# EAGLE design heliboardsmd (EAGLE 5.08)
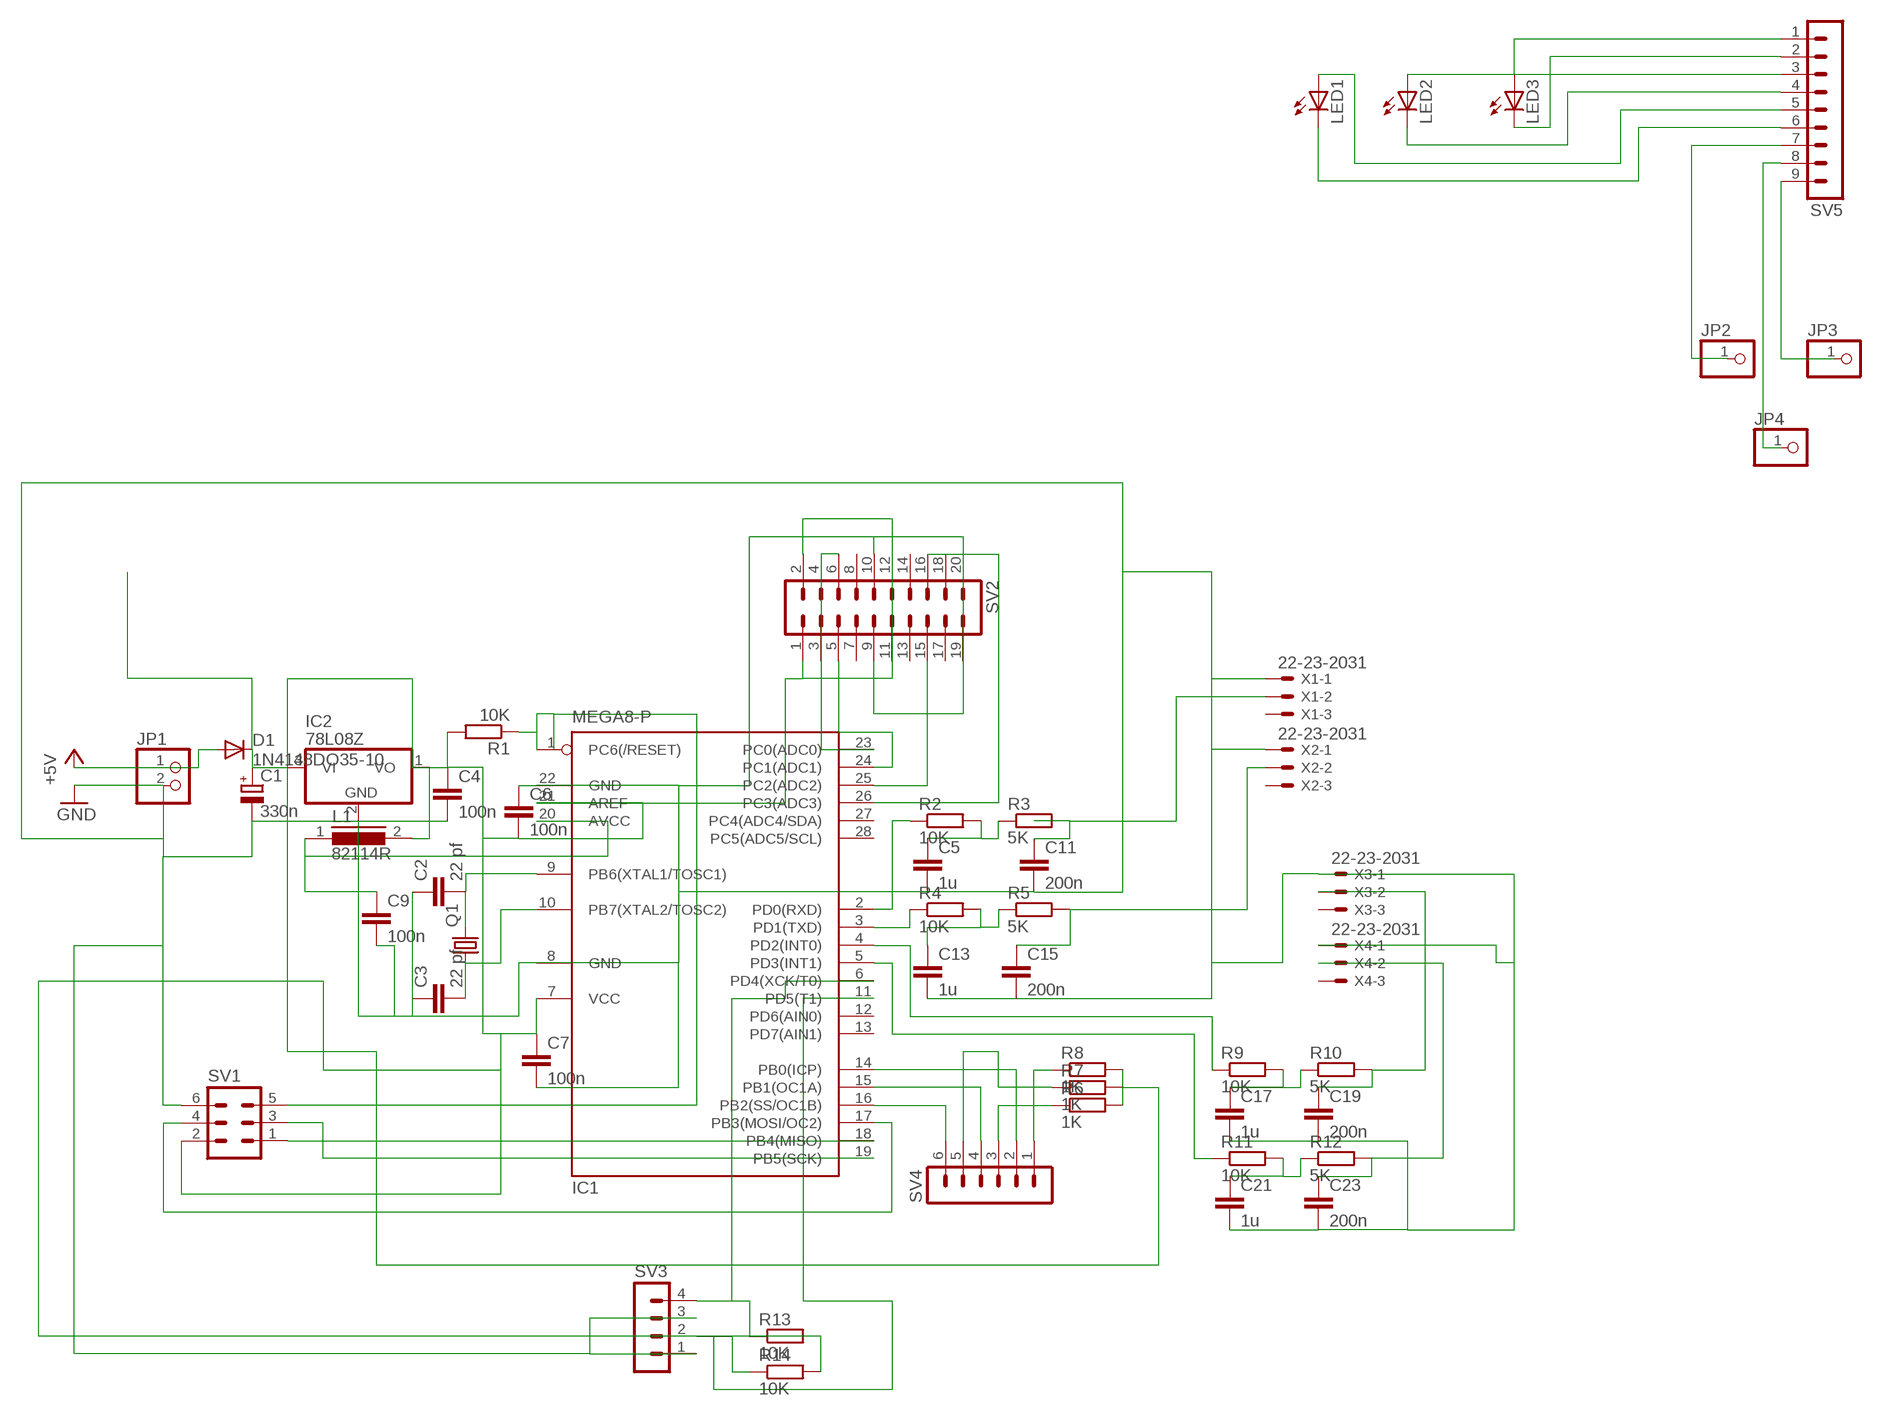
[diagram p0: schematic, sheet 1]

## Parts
C1  330n  CPOL-EUE1.8-4  [E1,8-4]
C2  22 pf  C-EUC0805K  [C0805K]
C3  22 pf  C-EUC0805K  [C0805K]
C4  100n  C-EUC0805K  [C0805K]
C5  1u  C-EUC1206K  [C1206K]
C6  100n  C-EUC0805K  [C0805K]
C7  100n  C-EUC0805K  [C0805K]
C9  100n  C-EUC0805K  [C0805K]
C11  200n  C-EUC1206K  [C1206K]
C13  1u  C-EUC1206K  [C1206K]
C15  200n  C-EUC1206K  [C1206K]
C17  1u  C-EUC1206K  [C1206K]
C19  200n  C-EUC1206K  [C1206K]
C21  1u  C-EUC1206K  [C1206K]
C23  200n  C-EUC1206K  [C1206K]
D1  1N4148DO35-10  [DO35-10]
IC1  MEGA8-P  [DIL28-3]
IC2  78L08Z  [TO92]
JP1  PINHD-1X2/90  [1X02/90]
JP2  PINHD-1X1  [1X01]
JP3  PINHD-1X1  [1X01]
JP4  PINHD-1X1  [1X01]
L1  82114R  [82114R]
LED1  LED3MM  [LED3MM]
LED2  LED3MM  [LED3MM]
LED3  LED3MM  [LED3MM]
Q1  CRYSTALHC18U-V  [HC18U-V]
R1  10K  R-EU_R1206  [R1206]
R2  10K  R-EU_M0805  [M0805]
R3  5K  R-EU_M0805  [M0805]
R4  10K  R-EU_M0805  [M0805]
R5  5K  R-EU_M0805  [M0805]
R6  1K  R-EU_M1206  [M1206]
R7  1K  R-EU_M1206  [M1206]
R8  1K  R-EU_M1206  [M1206]
R9  10K  R-EU_M0805  [M0805]
R10  5K  R-EU_M0805  [M0805]
R11  10K  R-EU_M0805  [M0805]
R12  5K  R-EU_M0805  [M0805]
R13  10K  R-EU_M0805  [M0805]
R14  10K  R-EU_M0805  [M0805]
SV1  MA03-2  [MA03-2]
SV2  MA10-2  [MA10-2]
SV3  MA04-1  [MA04-1]
SV4  MA06-1  [MA06-1]
SV5  MA09-1  [MA09-1]
X1  22-23-2031  [22-23-2031]
X2  22-23-2031  [22-23-2031]
X3  22-23-2031  [22-23-2031]
X4  22-23-2031  [22-23-2031]

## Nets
+5V: D1.A JP1.1
GND: C1.- C2.1 C3.1 C4.2 C5.2 C6.1 C7.2 C9.2 C11.2 C13.2 C15.2 C17.2 C19.2 C21.2 C23.2 IC1.8(GND) IC1.22(GND) IC2.2(GND) JP1.2 SV1.6 SV2.9 SV2.10 SV2.19 SV2.20 SV3.1 SV3.3 X1.1 X2.1 X3.1 X4.1
N$1: IC1.16(PB2(SS/OC1B)) SV4.6
N$2: C13.1 R4.2 R5.1
N$3: C1.+ D1.C IC2.3(VI)
N$4: C5.1 R2.2 R3.1
N$5: C19.1 R10.2 X3.2
N$7: C23.1 R12.2 X4.2
N$8: R7.1 SV4.5
N$9: C3.2 IC1.10(PB7(XTAL2/TOSC2)) Q1.1
N$10: C2.2 IC1.9(PB6(XTAL1/TOSC1)) Q1.2
N$11: IC1.15(PB1(OC1A)) SV4.4
N$12: R6.1 SV4.3
N$13: IC1.14(PB0(ICP)) SV4.2
N$14: R8.1 SV4.1
N$15: C4.1 C6.2 C7.1 IC1.7(VCC) IC1.21(AREF) IC2.1(VO) L1.2 R1.2 R6.2 R7.2 R8.2 R13.2 R14.2 SV1.2 SV2.1 SV2.2 SV2.11 SV2.12
N$16: IC1.18(PB4(MISO)) SV1.1
N$17: IC1.19(PB5(SCK)) SV1.3
N$18: IC1.17(PB3(MOSI/OC2)) SV1.4
N$19: IC1.2(PD0(RXD)) R2.1
N$20: C9.1 IC1.20(AVCC) L1.1
N$21: C15.1 R5.2 X2.2
N$23: LED3.A SV5.1
N$29: IC1.23(PC0(ADC0)) SV2.6
N$30: IC1.24(PC1(ADC1)) SV2.5
N$31: IC1.26(PC3(ADC3)) SV2.16
N$32: IC1.1(PC6(/RESET)) R1.1 SV1.5
N$33: IC1.25(PC2(ADC2)) SV2.15
N$35: IC1.3(PD1(TXD)) R4.1
N$36: LED3.K(C) SV5.2
N$37: C11.1 R3.2 X1.2
N$39: LED2.A SV5.3
N$41: LED2.K(C) SV5.4
N$42: IC1.4(PD2(INT0)) R9.1
N$43: IC1.5(PD3(INT1)) R11.1
N$44: LED1.A SV5.5
N$46: C17.1 R9.2 R10.1
N$48: C21.1 R11.2 R12.1
N$49: LED1.K(C) SV5.6
N$50: JP2.1 SV5.7
N$51: JP4.1 SV5.8
N$52: JP3.1 SV5.9
N$56: IC1.6(PD4(XCK/T0)) R13.1 SV3.4
N$57: IC1.11(PD5(T1)) R14.1 SV3.2
Unconnected: IC1.12(PD6(AIN0)) IC1.13(PD7(AIN1)) IC1.27(PC4(ADC4/SDA)) IC1.28(PC5(ADC5/SCL)) SV2.3 SV2.4 SV2.7 SV2.8 SV2.13 SV2.14 SV2.17 SV2.18 X1.3 X2.3 X3.3 X4.3

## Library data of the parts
C1 = rcl:CPOL-EU: POLARIZED CAPACITOR, European symbol
C2-C7 C9 C11 C13 C15 C17 C19 C21 C23 = resistor:C-EU: CAPACITOR, European symbol
D1 = diode:1N4148: DIODE
IC1 = atmel:MEGA8-P: MICROCONTROLLER 8 Kbytes FLASH, 1 kbytes SRAM, 512 bytes EEPROM, USART, 4-channel 10 bit ADC, 2-channel 8 bit ADC Pin compatible with Atmega48, ATMega88, ATMega168 Source: avr.lbr
IC2 = linear:78*: Positive VOLTAGE REGULATOR Source: http://cache.national.com/ds/LM/LM78L05.pdf http://www.fairchildsemi.com/ds/LM/LM7805.pdf
JP1 = pinhead:PINHD-1X2: PIN HEADER
JP2-JP4 = pinhead:PINHD-1X1: PIN HEADER
L1 = inductors:82114R: INDUCTOR
LED1-LED3 = led:LED: LED
Q1 = crystal:CRYSTAL: CRYSTAL
R1-R14 = resistor:R-EU_: RESISTOR, European symbol
SV1 = con-lstb:MA03-2: PIN HEADER
SV2 = con-lstb:MA10-2: PIN HEADER
SV3 = con-lstb:MA04-1: PIN HEADER
SV4 = con-lstb:MA06-1: PIN HEADER
SV5 = con-lstb:MA09-1: PIN HEADER
X1-X4 = con-molex:22-23-2031: .100" (2.54mm) Center Header - 3 Pin

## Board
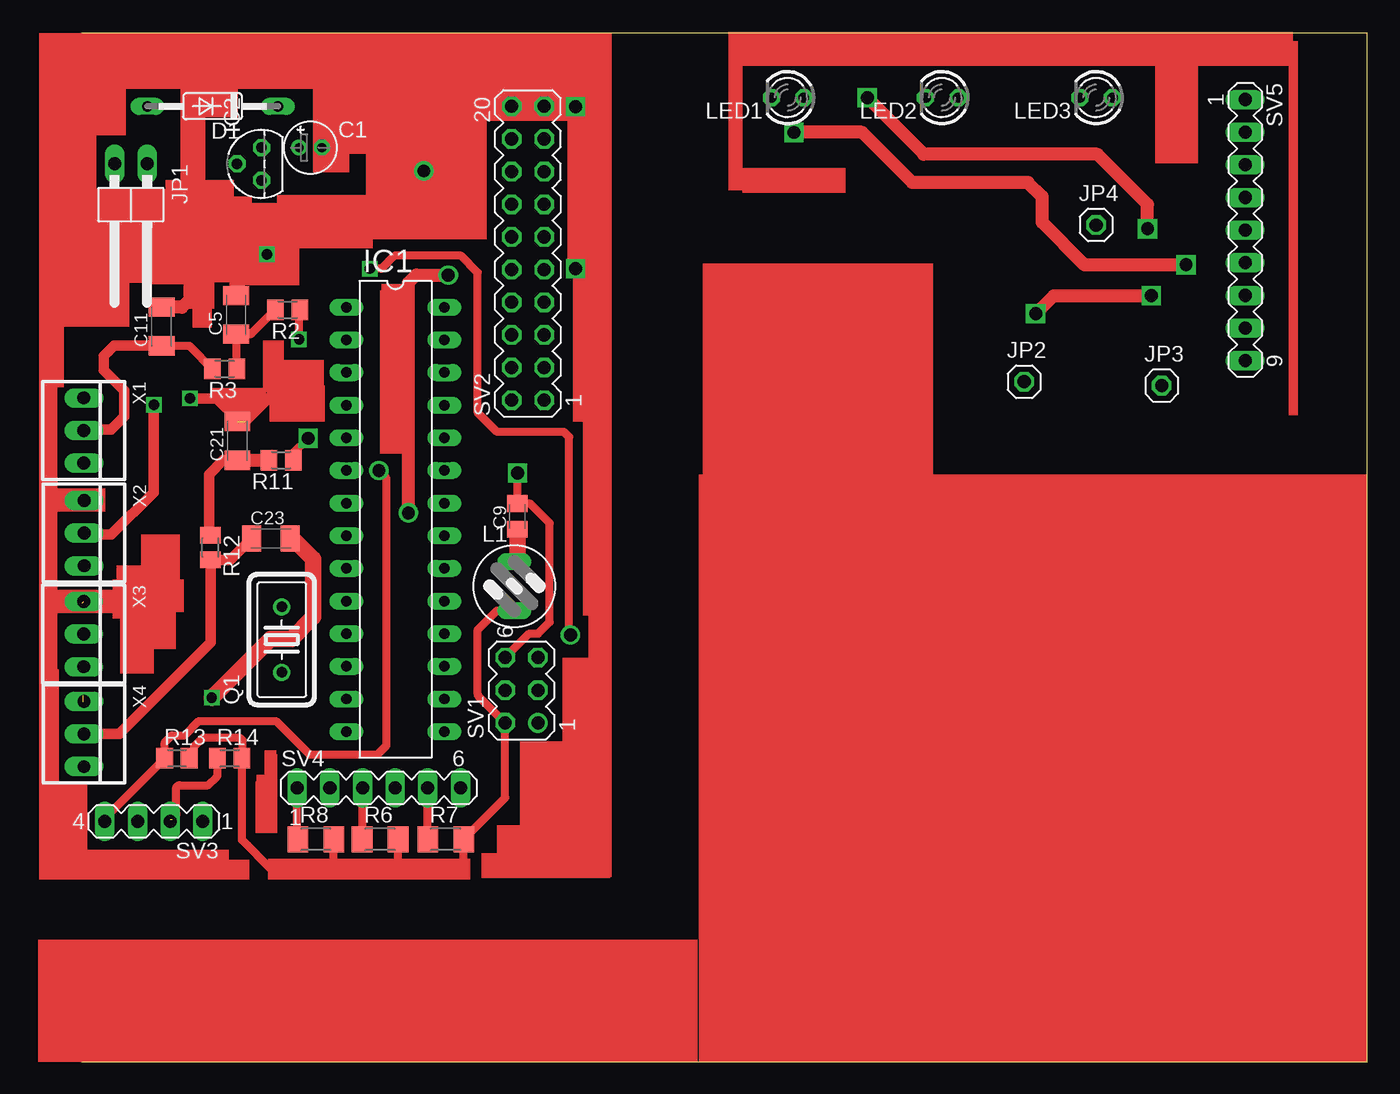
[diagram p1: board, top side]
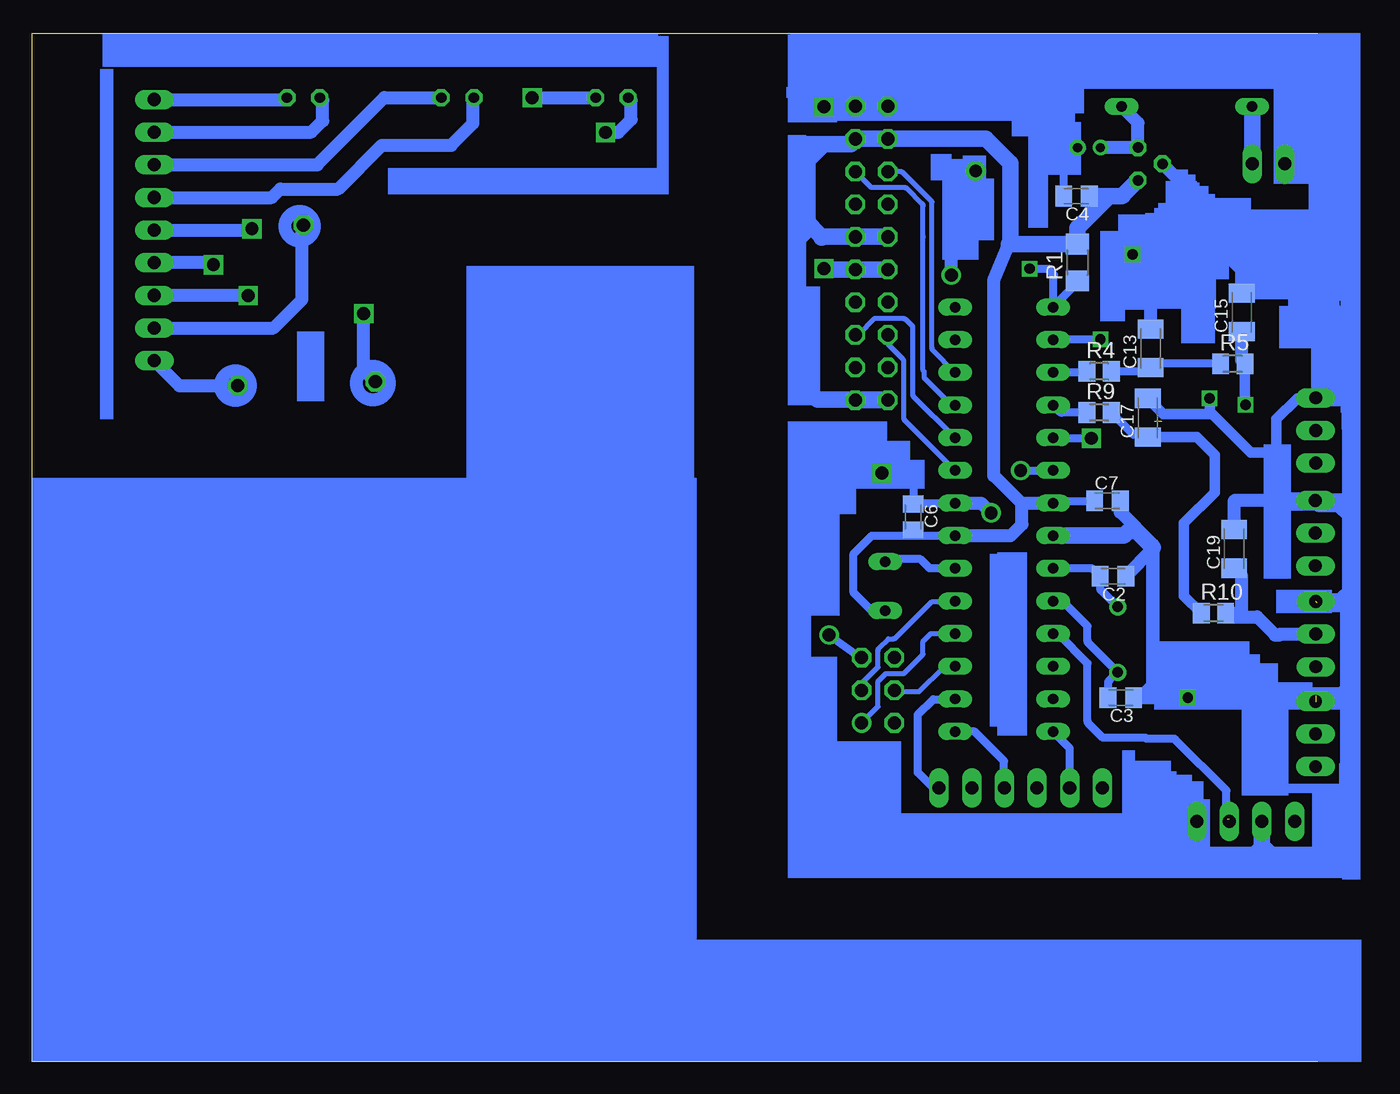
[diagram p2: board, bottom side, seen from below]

Size 100 x 80 mm. Coordinates in mm from the lower left corner, seen from the top.
Outline: 0,0 100,0 100,80 0,80
Copper layers (1*16): Top 0.035mm / dielectric 1.5mm / Bottom 0.035mm
Design rules "default *": minimum track width 10mil, minimum drill 24mil, track to track 8mil, track to pad 8mil, pad to pad 8mil, via to via 8mil, smd to smd 8mil, copper to edge 40mil, drill to drill 8mil, minimum pad ring 10mil, minimum via ring 8mil, stop-mask expansion 4mil, vias tented up to drill 0mil, thermal gap 10mil

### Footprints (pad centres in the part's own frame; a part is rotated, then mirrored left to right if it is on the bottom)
E1,8-4 = drill 0.711 pad 1.168 round: + -0.889,0 | drill 0.711 pad 1.168 octagon: - 0.889,0
C0805K = smd 1.3 x 1.6: 1 -1,0; 2 1,0
C1206K = smd 1.5 x 2: 1 -1.5,0; 2 1.5,0
DO35-10 = drill 0.813 long: A 5.08,0; C -5.08,0
DIL28-3 = drill 0.813 long: 1 -16.51,-3.81; 2 -13.97,-3.81; 3 -11.43,-3.81; 4 -8.89,-3.81; 5 -6.35,-3.81; 6 -3.81,-3.81; 7 -1.27,-3.81; 8 1.27,-3.81; 9 3.81,-3.81; 10 6.35,-3.81; 11 8.89,-3.81; 12 11.43,-3.81; 13 13.97,-3.81; 14 16.51,-3.81; 15 16.51,3.81; 16 13.97,3.81; 17 11.43,3.81; 18 8.89,3.81; 19 6.35,3.81; 20 3.81,3.81; 21 1.27,3.81; 22 -1.27,3.81; 23 -3.81,3.81; 24 -6.35,3.81; 25 -8.89,3.81; 26 -11.43,3.81; 27 -13.97,3.81; 28 -16.51,3.81
TO92 = drill 0.813 octagon: 1 -1.27,0; 2 0,1.905; 3 1.27,0
1X02/90 = drill 1.016 long: 1 -1.27,-3.81; 2 1.27,-3.81
1X01 = drill 1.016 octagon: 1 0,0
82114R = drill 0.813 long: 1 0,1.905; 2 0,-1.905
LED3MM = drill 0.813 octagon: A -1.27,0; K 1.27,0
HC18U-V = drill 0.813 round: 1 -2.54,0; 2 2.54,0
R1206 = smd 1.6 x 1.803: 1 -1.422,0; 2 1.422,0
M0805 = smd 1.3 x 1.6: 1 -0.95,0; 2 0.95,0
M1206 = smd 1.6 x 2: 1 -1.4,0; 2 1.4,0
MA03-2 = drill 1.016 round: 1 -2.54,-1.27 | drill 1.016 octagon: 2 -2.54,1.27; 3 0,-1.27; 4 0,1.27; 5 2.54,-1.27; 6 2.54,1.27
MA10-2 = drill 1.016 octagon: 1 -11.43,-1.27; 2 -11.43,1.27; 3 -8.89,-1.27; 4 -8.89,1.27; 5 -6.35,-1.27; 6 -6.35,1.27; 7 -3.81,-1.27; 8 -3.81,1.27; 9 -1.27,-1.27; 10 -1.27,1.27; 11 1.27,-1.27; 12 1.27,1.27; 13 3.81,-1.27; 14 3.81,1.27; 15 6.35,-1.27; 16 6.35,1.27; 17 8.89,-1.27; 18 8.89,1.27; 19 11.43,-1.27; 20 11.43,1.27
MA04-1 = drill 1.016 long: 1 -3.81,0; 2 -1.27,0; 3 1.27,0; 4 3.81,0
MA06-1 = drill 1.016 long: 1 -6.35,0; 2 -3.81,0; 3 -1.27,0; 4 1.27,0; 5 3.81,0; 6 6.35,0
MA09-1 = drill 1.016 long: 1 -10.16,0; 2 -7.62,0; 3 -5.08,0; 4 -2.54,0; 5 0,0; 6 2.54,0; 7 5.08,0; 8 7.62,0; 9 10.16,0
22-23-2031 = drill 1 long: 1 -2.54,0; 2 0,0; 3 2.54,0

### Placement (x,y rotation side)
C1  17.78,71.12 0 top
C2  15.91,37.76 180 bottom
C3  15.31,28.32 180 bottom
C4  18.76,67.34 180 bottom
C5  12,58.1 90 top
C6  31.46,42.38 270 bottom
C7  16.35,43.64 0 bottom
C9  33.88,42.43 90 top
C11  6.2,57.2 90 top
C13  13,55.5 90 bottom
C15  5.9,58.3 90 bottom
C17  13.2,50.1 90 bottom
C19  6.5,39.9 90 bottom
C21  12.1,48.3 90 top
C23  14.7,40.7 0 top
D1  10.17,74.33 180 top
IC1  24.39,42.19 270 top
IC2  13.97,69.85 90 top
JP1  3.81,66.04 180 top
JP2  73.3,52.9 0 top
JP3  84,52.6 0 top
JP4  78.9,65.1 0 top
L1  33.65,37 0 top
LED1  54.9,75 180 top
LED2  66.9,75 180 top
LED3  78.9,75 180 top
Q1  15.55,32.84 90 top
R1  18.69,62.19 90 bottom
R2  16,58.5 180 top
R3  11.1,53.9 180 top
R4  17,53.7 0 bottom
R5  6.6,54.3 0 bottom
R6  23.2,17.3 0 top
R7  28.3,17.3 0 top
R8  18.2,17.3 0 top
R9  17,50.5 0 bottom
R10  8.1,34.9 0 bottom
R11  15.5,46.8 180 top
R12  10,40 270 top
R13  7.4,23.6 0 top
R14  11.5,23.6 0 top
SV1  34.2,28.9 90 top
SV2  34.7,62.9 90 top
SV3  5.6,18.7 180 top
SV4  23.1,21.3 0 top
SV5  90.5,64.7 270 top
X1  0.15,49.11 270 top
X2  0.17,41.12 270 top
X3  0.14,33.27 270 top
X4  0.16,25.5 270 top

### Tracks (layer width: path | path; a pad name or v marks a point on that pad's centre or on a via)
+5V
  Bottom 0.61: 5.08,74.31 arc-45 D1.A
  Bottom 1.27: JP1.1 5.08,74.31 arc-45 D1.A
GND  (via drill 0.8, 1)  (3 unrouted)
  Top 0.61: SV1.6 34.79,33.3 35.5,33.3 36.4,34.2 36.4,41.9 34.87,43.43 C9.2 33.9,43.44 v33.9,45.8
  Top 0.813: 12.7,49.8 15.4,52.5 15.4,52.3 | C21.2 12.1,50 10.5,51.6 v8.4,51.6
  Top 1.016: v25.4,42.7 25.4,60.6 26,61.2 v28.5,61.2 | v26.6,69.3 24.78,71.12 C1.- | C11.2 7.8,58.7 9.1,60 9.1,60.1 10.1,61.1 11.8,61.1 12,60.9 C5.2 12,60.4 v14.4,62.8
  Top 1.27: v38.4,74.3 v38.4,61.7 | C23.2 16.4,40.7 18,39.1 18,34.6 16.3,32.9 14.68,32.9 v10.1,28.32
  Bottom 0.61: IC1.22 31.27,43.46 arc-45 C6.1 31.46,44.86 32.4,45.8 v33.9,45.8 | C1.- 19.69,70.1 arc-45 19.76,69.92 C4.2 | 0.73,28.5 0.16,28.5
  Bottom 0.813: 0.2,51.6 1.6,51.6 3.2,50 3.2,47.6 3.4,47.4 5.2,47.4 8.2,50.4 | 8.2,50.4 12,50.4 C17.2 | v8.4,51.6 8.4,50.6 8.2,50.4 | 15.08,40.92 14.4,41.6 14.2,41.6 12.7,40.1 12.7,29.1 11.8,28.2 0.3,28.2 0.1,28
  Bottom 1.016: IC1.22 26.16,43.46 v25.4,42.7 | v28.5,61.2 28.5,67.4 v26.6,69.3 | C19.2 6.5,43.6 6.44,43.66 X2.1 | X1.1 0.2,51.6 | C7.2 15.35,42.75 12.8,40.2 12.8,40 12.8,39.87 | 12.8,39.87 C2.1 | v10.1,28.32 13.8,28.32 | 13.8,28.32 C3.1 | 12.8,39.87 12.8,29.32 13.8,28.32 | -0.1,59.8 C15.2 5.9,61.6 8.2,63.9 8.2,65.98 9.62,67.4 | -0.1,59.8 -2.5,57.4 -2.5,51.65 | -0.1,59.8 -0.5,59.8 -1.7,61 -1.7,65.2 -1.8,65.3 | v14.4,62.8 14.2,62.8 12.5,64.5 12.4,64.5 | 12.4,64.5 9.5,67.4 9.62,67.4 | 9.62,67.4 IC2.2 | C13.2 13,63.9 12.4,64.5
  Bottom 1.27: JP1.2 0.56,69.85 arc45 0.38,69.78 -1.8,67.6 -1.8,65.3 -1.8,65 arc45 -1.73,64.82 | 0.73,28.5 -1.79,28.5 arc-45 -1.97,28.57 -2.4,29 -2.4,29.9 | -2.4,29.9 -2.4,35.2 arc-45 -2.33,35.37 -2.1,35.6 -0.17,35.6 arc45 0.01,35.67 | SV2.10 SV2.9 38.33,61.63 v38.4,61.7 | C1.- 21.8,74.26 arc-45 21.98,74.33 SV2.20 SV2.19 38.37,74.33 v38.4,74.3 | -2.4,29.9 arc-45 -2.37,29.84 -2.37,21.67 arc-45 -2.3,21.5 -2.3,16.7 -1.57,15.97 arc45 -1.4,15.9 3.4,15.9 4.26,16.76 arc45 4.33,16.93 SV3.3 4.33,16.67 5.3,15.7 8.6,15.7 9.4,16.5 SV3.1 | -1.7,35.81 arc-45 -1.88,35.88 -2.6,36.6 | -2.6,36.6 -2.6,42.4 arc-45 -2.53,42.57 -1.7,43.4 -0.19,43.4 arc45 -0.01,43.47 X2.1 0.17,43.6 -2.6,43.6 -2.6,49.3 -2.5,49.3 -2.5,51.65 X1.1 | -2.6,35.81 X3.1 | -2.6,35.81 -2.6,36.6 | -2.6,35.81 -2.6,28.04 X4.1 0.44,28.32 v10.1,28.32 | IC1.8 15.08,40.92 14.7,41.3 14.1,41.3 12.8,40
N$1
  Bottom 0.61: IC1.16 28.23,28.2 29.9,28.2 31.1,27 31.1,22.5 29.9,21.3 SV4.6
N$2
  Bottom 0.61: R5.1 12.7,54.3 arc-90 C13.1 arc90 13.3,53.7 R4.2
N$3
  Bottom 1.016: D1.C 13.97,73.05 IC2.3 C1.+
N$4
  Top 0.61: R2.2 13.22,56.67 arc-45 13.04,56.6 C5.1 arc-45 12.05,56.48 R3.1
N$5
  Bottom 1.016: C19.1 5.9,37.8 5.9,34.6 6.2,34.9 R10.2 6.85,34.6 4.7,34.6 3.3,33.2 3,33.2 2.93,33.27 X3.2
N$7
  Top 0.813: X4.2 2.9,25.5 10,32.6 R12.2 11.55,39.05 C23.1
N$8
  Top 0.61: SV4.5 R7.1
N$9
  Bottom 0.61: IC1.10 19.95,35.84 arc45 19.77,35.77 17.9,33.9 17.9,32.76 arc-45 17.83,32.58 Q1.1 16.24,29.61 arc-45 16.31,29.43 C3.2
N$10
  Bottom 0.61: IC1.9 17.64,38.38 arc45 17.46,38.31 C2.2 16.91,36.84 arc-45 16.84,36.67 Q1.2
N$11
  Bottom 0.61: IC1.15 26.68,25.68 24.4,23.4 24.4,21.33 SV4.4
N$12
  Top 0.61: SV4.3 21.83,17.33 R6.1
N$13
  Bottom 0.61: IC1.14 19.29,24.39 SV4.2
N$14
  Top 0.61: SV4.1 16.75,17.35 R8.1
N$15
  Top 0.61: R13.2 arc-45 8.44,23.57 8.5,23.5 8.5,23.59 arc-45 8.57,23.77 8.7,23.9 8.7,24.39 arc-45 8.77,24.57 9.4,25.2 12.2,25.2 arc-45 12.37,25.13 12.5,25 12.5,23.72 arc-45 R14.2 12.45,17.25 14.8,14.9 19,14.9 19.6,15.5 | 33.66,35.1 arc45 L1.2 32.4,35.09 arc45 32.22,35.02 30.8,33.6 30.8,28.59 arc45 30.87,28.42 SV1.2 32.93,20.53 R7.2 29.7,15.4 28.8,14.5 25.5,14.5 24.6,15.4 | 19.6,15.5 R8.2 | 19.6,15.5 20.4,14.7 23.9,14.7 24.6,15.4 | 24.6,15.4 R6.2
  Bottom 0.61: C7.1 20.3,43.64 arc-45 20.48,43.57 IC1.7 | 30.89,40.92 IC1.21 | 30.89,40.92 arc45 31.07,41 C6.2 | SV2.1 36.03,51.41 arc-45 36.1,51.23 36.1,51.4 | L1.2 34.7,35.09 36.1,36.5 36.1,39.5 34.68,40.92 30.89,40.92
  Bottom 1.016: 23,43.46 IC1.7 | 23,43.46 23.06,43.46 25.2,45.6 25.2,60.8 24,63.6 | IC1.21 23.92,40.92 23.9,40.9 23,41.8 23,43.46
  Bottom 1.27: SV2.12 SV2.11 38.42,64.17 arc-45 38.6,64.1 38.6,64.2 39.25,64.85 | 36.2,51.5 36.04,51.5 | 36.04,51.5 arc45 SV2.1 SV2.2 33.46,51.5 36.04,51.5 | 23.6,63.61 23.98,63.61 arc-45 24,63.6 | 23.6,63.61 R1.2 18.69,64.75 arc45 18.61,64.93 16.2,67.34 | 16.2,67.34 15.31,67.34 arc-45 15.13,67.42 IC2.1 | 16.2,67.34 C4.1 | 23.6,63.61 23.9,63.91 23.9,69.9 25.8,71.8 35.9,71.8 36.3,71.4 38.4,71.4 39.7,70.1 39.7,65.3 39.25,64.85 | 36.2,51.5 36.1,51.4 | 36.2,51.5 38.9,51.5 40.5,53.1 40.5,63.9 39.55,64.85 39.25,64.85
N$16
  Bottom 0.406: SV1.1 34.2,27.63 34.2,29.6 33.6,30.2 32.2,30.2 30.7,31.7 30.7,32.7 30.1,33.3 IC1.18
N$17
  Bottom 0.406: SV1.3 35.47,29.32 arc45 35.4,29.5 34.2,30.7 34.2,32 arc45 34.13,32.17 33.4,32.9 33.01,32.9 arc-45 32.83,32.97 30,35.8 28.3,35.8 arc-45 IC1.19
N$18
  Bottom 0.406: IC1.17 28.93,30.76 arc-45 29.11,30.69 31,28.8 32.73,28.8 arc45 32.9,28.87 SV1.4
N$19  (via drill 0.8)
  Top 0.61: v16.9,56.2 16.9,58.38 arc-45 R2.1
  Bottom 0.61: IC1.2 16.99,56.16 arc-45 v16.9,56.2
N$20
  Top 1.27: C9.1 33.88,39.14 L1.1
  Bottom 0.61: IC1.20 30.08,38.38 arc45 30.26,38.46 30.9,39.1 33.35,39.1 arc-45 33.53,39.03 L1.1
N$21  (via drill 0.8)
  Top 0.813: v5.6,51.1 5.6,44.3 2.3,41 0.29,41 X2.2
  Bottom 0.813: R5.2 5.65,51.15 v5.6,51.1
  Bottom 1.016: R5.2 5.9,54.55 C15.1
N$23
  Bottom 1.016: SV5.1 80.17,74.86 LED3.A
N$29
  Bottom 0.406: SV2.6 33.43,55.94 arc-45 33.36,55.76 32.27,54.67 arc45 32.2,54.49 32.2,50.1 arc-45 32.13,49.92 IC1.23
N$30
  Bottom 0.406: SV2.5 35.85,56.55 arc-45 35.68,56.62 34.5,57.8 32.2,57.8 arc45 32.03,57.73 31.5,57.2 31.5,51.95 arc-45 31.43,51.77 IC1.24
N$31
  Bottom 0.406: IC1.26 29.93,55.34 arc45 30,55.52 30,66.9 32.28,69.18 arc-45 32.45,69.25 SV2.16
N$32  (via drill 0.8, 1)
  Top 0.61: v22.4,61.7 23.3,61.7 24.3,62.7 29.5,62.7 30.8,61.4 30.8,50.5 32.3,49 37.5,49 37.9,48.6 37.9,33.3 v38,33.2
  Bottom 0.61: R1.1 18.69,60.7 arc45 18.76,60.52 IC1.1 20.58,61.01 arc45 20.51,61.19 20.5,61.2 20.93,61.63 arc-45 21.11,61.7 v22.4,61.7 | v38,33.2 35.51,31.4 SV1.5
N$33
  Bottom 0.406: SV2.15 34.79,68.07 arc-45 34.62,68 32.1,68 arc45 31.93,67.93 30.77,66.77 arc45 30.7,66.59 30.7,64.2 30.67,64.17 arc-45 30.7,64.11 30.7,53.8 30.67,53.77 arc45 30.6,53.59 30.6,53.2 28.56,51.16 arc-45 28.38,51.08 IC1.25
N$35
  Bottom 0.61: R4.1 arc90 18.03,53.62 IC1.3
N$36
  Bottom 1.016: SV5.2 78.28,72.32 77.4,73.2 77.4,74.77 LED3.K
N$37
  Top 0.61: C11.1 8.24,55.7 arc-45 8.42,55.63 R3.2
  Top 0.813: C11.1 2.5,55.7 1.7,54.9 1.7,53.8 3.3,52.2 3.3,50.2 2.3,49.2 0.24,49.2 X1.2
N$39
  Bottom 1.016: SV5.3 77.82,69.78 72.6,75 LED2.A
N$41
  Bottom 1.016: SV5.4 81.36,67.24 80.7,67.9 76.2,67.9 72.8,71.3 67.4,71.3 65.7,73 65.7,74.93 LED2.K
N$42
  Bottom 0.61: R9.1 19.89,50.5 arc45 20.07,50.57 IC1.4
N$43  (via drill 1)
  Top 0.61: R11.1 16.45,47.35 v17.6,48.5
  Bottom 0.61: v17.6,48.5 20.54,48.5 IC1.5
N$44  (via drill 1)
  Top 1.016: v82.9,64.8 82.9,66.7 79,70.6 65.5,70.6 v61.1,75
  Bottom 1.016: SV5.5 83,64.7 v82.9,64.8 | v61.1,75 LED1.A
N$46
  Bottom 0.254: R9.2 16,50.29 | C17.1 13.21,48.77
  Bottom 0.61: 13.21,48.77 14.21,48.77 arc45 14.39,48.84 R9.2
  Bottom 0.813: C17.1 9.4,48.6 8,47.2 8,44.3 10.4,41.9 10.4,36.25 R10.1
N$48
  Top 0.813: C21.1 11,46.8 9.9,45.7 9.9,41.05 R12.1
  Top 1.016: C21.1 R11.2
N$49  (via drill 1)
  Top 1.016: v85.9,62 78,62 74.7,65.3 74.7,67.3 73.6,68.4 64.6,68.4 60.7,72.3 v55.4,72.3
  Bottom 1.016: SV5.6 86.06,62.16 v85.9,62 | v55.4,72.3 54.4,72.3 53.4,73.3 53.4,74.77 LED1.K
N$50  (via drill 1)
  Top 1.016: v83.2,59.6 75.6,59.6 v74.2,58.2
  Bottom 1.016: SV5.7 83.22,59.62 v83.2,59.6 | v74.2,58.2 74.2,53.8 JP2.1
N$51
  Bottom 1.016: SV5.8 81.22,57.08 79,59.3 79,65 JP4.1
N$52
  Bottom 1.016: SV5.9 88.56,52.6 JP3.1
N$56  (via drill 1)
  Top 0.61: SV3.4 1.79,18.84 arc-45 1.86,19.01 R13.1 6.45,24.85 7,25.4 8,25.4 9.1,26.5 15.1,26.5 17.7,23.9 23,23.9 23.7,24.6 23.7,45.4 v23.1,46
  Bottom 0.61: IC1.6 v23.1,46
N$57  (1 unrouted)
  Top 0.61: 6.94,19.04 arc45 6.87,18.86 SV3.2 7.28,19.11 arc45 7.35,19.29 7.35,21.35 7.43,21.43 arc-45 7.61,21.5 9.8,21.5 10.48,22.18 arc45 10.55,22.36 R14.1
  Bottom 0.61: IC1.11 20.31,33.3 arc45 20.13,33.23 17.9,31 17.9,26.5 arc-45 17.83,26.33 16.7,25.2 13.47,25.2 arc45 13.3,25.13 11.23,25.13 arc45 11.05,25.05 7.1,21.1 7.1,19.04 arc-45 7.03,18.86
(copper drawn outside any net)
  shapes: Bottom area x94, Bottom circle x4, Top area x77

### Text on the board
Bottom: Heli Mixer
